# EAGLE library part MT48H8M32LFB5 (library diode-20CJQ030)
Micron's Mobile SDRAM MT48H8M32LF ? 2 Meg x 32 x 4 banks Description: The Micron® 256Mb Mobile SDRAM is a high-speed CMOS, dynamic random-access memory containing 268,435,456-bits. It is internally configured as a quad-bank DRAM with a synchronous interface (all signals are registered on the positive edge of the clock signal, CLK). Each of the x16?s 67,108,864-bit banks is organized as 8,192 rows by 512K columns by 16 bits. Each of the x32?s 67,108,864-bit banks is organized as 4,096 rows by 256 columns by 32 bits. Read and write accesses to the SDRAM are burst oriented; accesses start at a selected location and continue for a programmed number of locations in a programmed sequence. Accesses begin with the registration of an ACTIVE command, which is then followed by a READ or WRITE command. The address bits registered coincident with the ACTIVE command are used to select the bank and row to be accessed (BA0, BA1 select the bank; A0?A12 select the row). The address bits registered coincident with the READ or WRITE command are used to select the starting column location for the burst access. The SDRAM provides for programmable read or write BLs of 1, 2, 4, 8, or full page locations with a read burst terminate option. An auto precharge function may be enabled to provide a self-timed row precharge that is initiated at the end of the burst sequence. The 256Mb SDRAM uses an internal pipelined architecture to achieve high-speed operation. This architecture is compatible with the 2n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
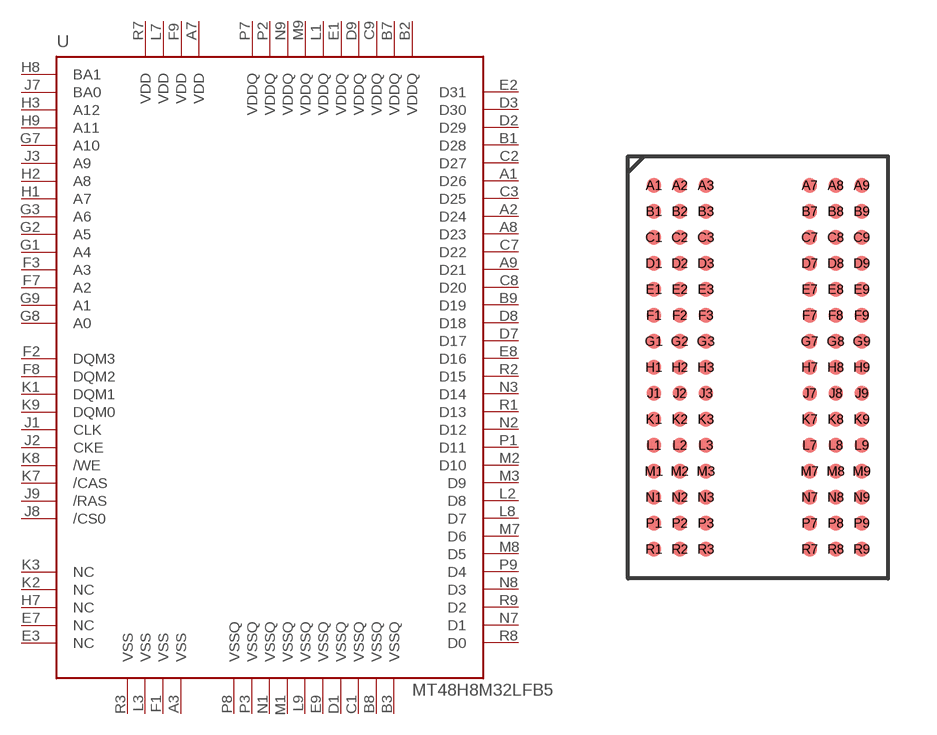
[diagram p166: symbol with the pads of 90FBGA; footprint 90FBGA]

Designator prefix U

## MT48H8M32LFB5  [90FBGA]
A1  D26
A2  D24
A3  VSS  pwr
A7  VDD  pwr
A8  D23
A9  D21
B1  D28
B2  VDDQ  pwr
B3  VSSQ  pwr
B7  VDDQ  pwr
B8  VSSQ  pwr
B9  D19
C1  VSSQ  pwr
C2  D27
C3  D25
C7  D22
C8  D20
C9  VDDQ  pwr
D1  VSSQ  pwr
D2  D29
D3  D30
D7  D17
D8  D18
D9  VDDQ  pwr
E1  VDDQ  pwr
E2  D31
E3  NC  nc
E7  NC  nc
E8  D16
E9  VSSQ  pwr
F1  VSS  pwr
F2  DQM3  in
F3  A3  in
F7  A2  in
F8  DQM2  in
F9  VDD  pwr
G1  A4  in
G2  A5  in
G3  A6  in
G7  A10  in
G8  A0  in
G9  A1  in
H1  A7  in
H2  A8  in
H3  A12  in
H7  NC  nc
H8  BA1  in
H9  A11  in
J1  CLK  in
J2  CKE  in
J3  A9  in
J7  BA0  in
J8  /CS0  in
J9  /RAS  in
K1  DQM1  in
K2  NC  nc
K3  NC  nc
K7  /CAS  in
K8  /WE  in
K9  DQM0  in
L1  VDDQ  pwr
L2  D8
L3  VSS  pwr
L7  VDD  pwr
L8  D7
L9  VSSQ  pwr
M1  VSSQ  pwr
M2  D10
M3  D9
M7  D6
M8  D5
M9  VDDQ  pwr
N1  VSSQ  pwr
N2  D12
N3  D14
N7  D1
N8  D3
N9  VDDQ  pwr
P1  D11
P2  VDDQ  pwr
P3  VSSQ  pwr
P7  VDDQ  pwr
P8  VSSQ  pwr
P9  D4
R1  D13
R2  D15
R3  VSS  pwr
R7  VDD  pwr
R8  D0
R9  D2

## Footprint 90FBGA (pad centres in mm)
90 PIN FBGA Pitch: 0.8mm balldiameter 0.5mm Please send any comments to: messi@users.sourceforge.net
smd 0.45 x 0.45: A1 -3.2,5.6; A2 -2.4,5.6; A3 -1.6,5.6; A7 1.6,5.6; A8 2.4,5.6; A9 3.2,5.6; B1 -3.2,4.8; B2 -2.4,4.8; B3 -1.6,4.8; B7 1.6,4.8; B8 2.4,4.8; B9 3.2,4.8; C1 -3.2,4; C2 -2.4,4; C3 -1.6,4; C7 1.6,4; C8 2.4,4; C9 3.2,4; D1 -3.2,3.2; D2 -2.4,3.2; D3 -1.6,3.2; D7 1.6,3.2; D8 2.4,3.2; D9 3.2,3.2; E1 -3.2,2.4; E2 -2.4,2.4; E3 -1.6,2.4; E7 1.6,2.4; E8 2.4,2.4; E9 3.2,2.4; F1 -3.2,1.6; F2 -2.4,1.6; F3 -1.6,1.6; F7 1.6,1.6; F8 2.4,1.6; F9 3.2,1.6; G1 -3.2,0.8; G2 -2.4,0.8; G3 -1.6,0.8; G7 1.6,0.8; G8 2.4,0.8; G9 3.2,0.8; H1 -3.2,0; H2 -2.4,0; H3 -1.6,0; H7 1.6,0; H8 2.4,0; H9 3.2,0; J1 -3.2,-0.8; J2 -2.4,-0.8; J3 -1.6,-0.8; J7 1.6,-0.8; J8 2.4,-0.8; J9 3.2,-0.8; K1 -3.2,-1.6; K2 -2.4,-1.6; K3 -1.6,-1.6; K7 1.6,-1.6; K8 2.4,-1.6; K9 3.2,-1.6; L1 -3.2,-2.4; L2 -2.4,-2.4; L3 -1.6,-2.4; L7 1.6,-2.4; L8 2.4,-2.4; L9 3.2,-2.4; M1 -3.2,-3.2; M2 -2.4,-3.2; M3 -1.6,-3.2; M7 1.6,-3.2; M8 2.4,-3.2; M9 3.2,-3.2; N1 -3.2,-4; N2 -2.4,-4; N3 -1.6,-4; N7 1.6,-4; N8 2.4,-4; N9 3.2,-4; P1 -3.2,-4.8; P2 -2.4,-4.8; P3 -1.6,-4.8; P7 1.6,-4.8; P8 2.4,-4.8; P9 3.2,-4.8; R1 -3.2,-5.6; R2 -2.4,-5.6; R3 -1.6,-5.6; R7 1.6,-5.6; R8 2.4,-5.6; R9 3.2,-5.6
